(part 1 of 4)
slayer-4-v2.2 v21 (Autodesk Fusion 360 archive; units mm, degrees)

design "slayer-4-v2.2" references "EACHINE CCW TYRO79-1607-2800KV", "M2 x 0.4mm Thread 5mm LONG SOCKET HEAD CAP SCREW", "20x20 Flight Controller", "M3 x 0.5mm Thread 6mm LONG SOCKET HEAD CAP SCREW", "runcam_phoenix_2", "CADDXFPV Ratel 2.1mm", "Slayer Hurricane 4040"
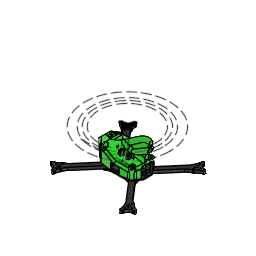
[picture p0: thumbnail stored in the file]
parameter "armstrength" = 5
parameter "d11" = 33
parameter "d12" = 48
parameter "d547" = 2
sketch "center-upper" plane through (0, 0, 0) normal (0, 0, 1) x axis (1, 0, 0)
  line L1 (-93, 0) -> (0, 0)
  line L2 (0, 100) -> (0, 0)
  line L3 (-24, 16.5) -> (-18.1019, 0)
  line L4 (0, 18.1019) -> (-24, 16.5)
  line L5 (0, 18.1019) -> (-10, 10)
  line L6 (-10, 10) -> (-18.1019, 0)
  line L7 (-25.4125, 15.9951) -> (-19.6949, 0)
  line L8 (-22.5875, 17.0049) -> (-16.509, 0)
  line L9 (-11.1655, 10.9443) -> (-20.0325, 0)
  line L10 (-8.8345, 9.0557) -> (-16.1714, 0)
  line L11 (-10.9443, 11.1655) -> (-0.9443, 19.2674)
  line L12 (-9.0557, 8.8345) -> (0.9443, 16.9364)
  line L13 (-35, 0) -> (0, 0)
  line L14 (-22.5875, 17.0049) -> (-24, 16.5)
  line L15 (-25.4125, 15.9951) -> (-24, 16.5)
  line L16 (-11.1655, 10.9443) -> (-10, 10)
  line L17 (-8.8345, 9.0557) -> (-10, 10)
  line L18 (-10.9443, 11.1655) -> (-10, 10)
  line L19 (-9.0557, 8.8345) -> (-10, 10)
  line L20 (-0.9443, 19.2674) -> (0, 18.1019)
  line L21 (0.9443, 16.9364) -> (0, 18.1019)
  line L22 (0.0999, 16.6053) -> (-23.9001, 15.0033)
  line L23 (-0.0999, 19.5986) -> (-24.0999, 17.9967)
  line L24 (-24.0999, 17.9967) -> (-24, 16.5)
  line L25 (-23.9001, 15.0033) -> (-24, 16.5)
  line L26 (-0.0999, 19.5986) -> (0, 18.1019)
  line L27 (0.0999, 16.6053) -> (0, 18.1019)
  line L28 (0, 30) -> (0, 0)
  line L29 (0, 1.5) -> (-18.1019, 1.5)
  line L30 (-18.1019, 1.5) -> (-18.1019, 0)
  line L31 (0, 0) -> (-10, 10)
  line L32 (-14.1459, 2.5) -> (0, 2.5)
  line L33 (-7.5042, 2.5) -> (-10, 10)
  curve K1
  circle C1 centre (-24, 16.5) radius 1.55
  circle C2 centre (0, 18.1019) radius 1.05
  circle C3 centre (-18.1019, 0) radius 1.05
  circle C4 centre (-10, 10) radius 1.05
  circle C5 centre (-24, 16.5) radius 4
  circle C6 centre (0, 18.1019) radius 3
  circle C7 centre (-10, 10) radius 3
  circle C8 centre (-18.1019, 0) radius 3
  point P3 (-24, 16.5)
  point P5 (-24, 16.5)
  point P1 (0, 0)
  point P6 (0, 0)
  point P4 (-18.1019, 0)
  point P8 (0, 0)
  point P2 (0, 18.1019)
  point P11 (-18.1019, 0)
  point P12 (-24, 16.5)
  point P13 (0, 18.1019)
  point P10 (-10, 10)
  point P14 (-10, 10)
  point P20 (-20.0325, 0)
  point P22 (-16.1714, 0)
  point P31 (0, 0)
  point P32 (-35, 0)
  point P33 (-24, 16.5)
  point P34 (-22.5875, 17.0049)
  point P19 (-24, 16.5)
  point P35 (-24, 16.5)
  point P36 (-25.4125, 15.9951)
  point P18 (-22.5875, 17.0049)
  point P16 (-25.4125, 15.9951)
  point P17 (-16.509, 0)
  point P15 (-19.6949, 0)
  point P29 (-10, 10)
  point P37 (-10, 10)
  point P38 (-11.1655, 10.9443)
  point P39 (-10, 10)
  point P40 (-8.8345, 9.0557)
  point P41 (-10, 10)
  point P42 (-10.9443, 11.1655)
  point P43 (-9.0557, 8.8345)
  point P25 (-10.9443, 11.1655)
  point P21 (-11.1655, 10.9443)
  point P23 (-8.8345, 9.0557)
  point P27 (-9.0557, 8.8345)
  point P44 (0, 18.1019)
  point P45 (-0.9443, 19.2674)
  point P46 (0.9443, 16.9364)
  point P24 (-0.9443, 19.2674)
  point P26 (0.9443, 16.9364)
  point P51 (-24.0999, 17.9967)
  point P52 (-24, 16.5)
  point P53 (-23.9001, 15.0033)
  point P49 (-24.0999, 17.9967)
  point P47 (-23.9001, 15.0033)
  point P28 (0, 18.1019)
  point P54 (0, 18.1019)
  point P55 (-0.0999, 19.5986)
  point P56 (0.0999, 16.6053)
  point P50 (-0.0999, 19.5986)
  point P48 (0.0999, 16.6053)
  point P57 (0, 30)
  point P60 (-18.1019, 0)
  point P61 (0, 2.5)
  point P62 (-14.1459, 2.5)
  point P63 (-7.5042, 2.5)
  coincident P3 P5
  coincident P1 P6
  coincident P4 L1
  coincident P1 P8
  coincident P2 L2
  coincident P4 P11
  coincident P3 P12
  coincident P2 P13
  coincident P10 P14
  parallel L3 L7
  parallel L3 L8
  concentric C1 C5
  coincident L1 P20
  parallel L6 L9
  coincident L1 P22
  parallel L6 L10
  parallel L5 L11
  parallel L5 L12
  concentric C2 C6
  concentric C4 C7
  concentric C3 C8
  coincident P1 P31
  coincident L1 P32
  perpendicular L2 L13
  coincident P3 P33
  coincident L8 P34
  perpendicular L8 L14
  coincident P19 P35
  coincident L7 P36
  perpendicular L7 L15
  coincident P18 P34
  coincident P16 P36
  coincident L1 P17
  coincident P15 L13
  coincident P29 P37
  coincident L9 P38
  perpendicular L9 L16
  coincident P10 P39
  coincident L10 P40
  perpendicular L10 L17
  coincident P29 P41
  coincident L11 P42
  perpendicular L11 L18
  coincident L12 P43
  perpendicular L12 L19
  coincident P25 L19
  coincident P21 P38
  coincident P23 P40
  coincident P27 P43
  coincident P2 P44
  coincident L11 P45
  perpendicular L11 L20
  coincident L12 P46
  perpendicular L12 L21
  coincident P24 P45
  coincident P26 P46
  parallel L4 L22
  parallel L4 L23
  coincident L23 P51
  perpendicular L23 L24
  coincident P3 P52
  coincident L22 P53
  perpendicular L22 L25
  coincident P49 P51
  coincident P47 P53
  coincident P28 P54
  coincident L23 P55
  perpendicular L23 L26
  coincident L22 P56
  perpendicular L22 L27
  coincident P50 P55
  coincident P48 P56
  coincident L2 P57
  horizontal L29
  coincident P4 P60
  perpendicular L29 L30
  coincident L28 P61
  coincident L10 P62
  perpendicular L28 L32
  coincident L32 P63
  dimension "d15" distance P2 P4 = 25.6
  dimension "d17" diameter C1 = 3.1
  dimension "d21" diameter C2 = 2.1
  dimension "d24" diameter C3 = 2.1 (= "d21")
  dimension "d27" distance P3 L1 = 16.5 (= "d11 / 2")
  dimension "d28" distance P3 L2 = 24 (= "d12 / 2")
  dimension "d34" diameter C4 = 2.1 (= "d21")
  dimension "d38" distance L2 P10 = 10
  dimension "d39" distance L1 P10 = 10
  dimension "d44" distance L3 L7 = 1.5
  dimension "d45" distance L3 L8 = 1.5 (= "d44")
  dimension "d47" distance L6 L9 = 1.5 (= "d44")
  dimension "d48" distance L6 L10 = 1.5 (= "d44")
  dimension "d49" distance L5 L11 = 1.5 (= "d44")
  dimension "d50" distance L5 L12 = 1.5 (= "d44")
  dimension "d51" diameter C5 = 8
  dimension "d52" diameter C8 = 6
  dimension "d53" diameter C7 = 6
  dimension "d54" diameter C6 = 6
  dimension "d55" distance L4 L23 = 1.5 (= "d44")
  dimension "d56" distance L4 L22 = 1.5 (= "d44")
  dimension "d93" distance L1 L29 = 1.5
  dimension "d118" distance L13 L32 = 2.5
extrude "Extrude2" new body sketch "center-upper" profile of C1 C2 C3 C4 L7 L8 C5 L9 L10 L11 L12 C6 C7 C8 L13 L22 L23 L28 along normal blind 2
fillet "Fillet6" radius 2
fillet "Fillet9" radius 5
fillet "Fillet7" radius 18
fillet "Fillet10" radius 20
mirror "Mirror1" mirrorStitchTolerance 0.1
mirror "Mirror2" mirrorStitchTolerance 0.1
fillet "Fillet8" radius 9
sketch "center-upper-rear-cage" plane through (0, 0, 0) normal (0, 0, -1) x axis (1, 0, 0)
  line L1 (-13.4582, 18.707) -> (-7.8768, 19.0795)
  line L2 (-7.8768, -19.0795) -> (-13.4582, -18.707)
  line L3 (13.4582, -18.707) -> (7.8768, -19.0795)
  line L4 (7.8768, 19.0795) -> (13.4582, 18.707)
  line L5 (19.6919, -8.9044) -> (18.7852, -6.3678)
  line L6 (13.4936, -15.6979) -> (15.3167, -15.5763)
  line L7 (15.3479, -5.782) -> (13.4133, -8.1699)
  line L8 (18.7852, 6.3678) -> (19.6919, 8.9044)
  line L9 (13.4133, 8.1699) -> (15.3479, 5.782)
  line L10 (15.3167, 15.5763) -> (13.4936, 15.6979)
  line L11 (-19.6919, 8.9044) -> (-18.7852, 6.3678)
  line L12 (-13.4936, 15.6979) -> (-15.3167, 15.5763)
  line L13 (-15.3479, 5.782) -> (-13.4133, 8.1699)
  line L14 (-18.7852, -6.3678) -> (-19.6919, -8.9044)
  line L15 (-13.4133, -8.1699) -> (-15.3479, -5.782)
  line L16 (-15.3167, -15.5763) -> (-13.4936, -15.6979)
  line L17 (19, 3) -> (31.9985, 3)
  line L18 (32.2887, 6) -> (20, 6)
  line L19 (34.9985, 7.3474) -> (27.3161, 18.7368)
  line L20 (34.9985, 0) -> (34.9985, 7.3474)
  line L21 (26.9948, 13.8484) -> (32.2887, 6)
  line L22 (31.9985, 0) -> (31.9985, 3)
  line L23 (34.9985, 0) -> (31.9985, 0)
  line L24 (20, 6) -> (19, 3)
  line L25 (27.3161, 18.7368) -> (26.9948, 13.8484)
  circle C1 centre (0, 18.1019) radius 1.05
  arc A1 centre (0, 18.1019) radius 3 clockwise from (-1.2965, 20.8073) to (1.2965, 20.8073)
  arc A2 centre (-9.0756, 37.0396) radius 18 clockwise from (-1.2965, 20.8073) to (-7.8768, 19.0795)
  arc A3 centre (-14.7902, 38.6626) radius 20 clockwise from (-13.4582, 18.707) to (-22.465, 20.1938)
  arc A4 centre (-24, 16.5) radius 4 clockwise from (-26.8498, 13.6931) to (-22.465, 20.1938)
  arc A5 centre (-41.099, -0.3411) radius 20 clockwise from (-26.8498, 13.6931) to (-21.1019, 0)
  arc A6 centre (-41.099, 0.3411) radius 20 clockwise from (-21.1019, 0) to (-26.8498, -13.6931)
  arc A7 centre (-24, -16.5) radius 4 clockwise from (-22.465, -20.1938) to (-26.8498, -13.6931)
  arc A8 centre (-14.7902, -38.6626) radius 20 clockwise from (-22.465, -20.1938) to (-13.4582, -18.707)
  arc A9 centre (-9.0756, -37.0396) radius 18 clockwise from (-7.8768, -19.0795) to (-1.2965, -20.8073)
  arc A10 centre (0, -18.1019) radius 3 clockwise from (1.2965, -20.8073) to (-1.2965, -20.8073)
  arc A11 centre (9.0756, -37.0396) radius 18 clockwise from (1.2965, -20.8073) to (7.8768, -19.0795)
  arc A12 centre (14.7902, -38.6626) radius 20 clockwise from (13.4582, -18.707) to (22.465, -20.1938)
  arc A13 centre (24, -16.5) radius 4 clockwise from (26.8498, -13.6931) to (22.465, -20.1938)
  arc A14 centre (41.099, 0.3411) radius 20 clockwise from (26.8498, -13.6931) to (21.1019, 0)
  arc A15 centre (41.099, -0.3411) radius 20 clockwise from (21.1019, 0) to (26.8498, 13.6931)
  arc A16 centre (24, 16.5) radius 4 clockwise from (22.465, 20.1938) to (26.8498, 13.6931)
  arc A17 centre (14.7902, 38.6626) radius 20 clockwise from (22.465, 20.1938) to (13.4582, 18.707)
  arc A18 centre (9.0756, 37.0396) radius 18 clockwise from (7.8768, 19.0795) to (1.2965, 20.8073)
  arc A19 centre (10, 10) radius 3 clockwise from (8.3417, 7.5) to (7.5, 8.3417)
  arc A20 centre (3.3668, 0) radius 9 clockwise from (8.3417, 7.5) to (8.3417, -7.5)
  arc A21 centre (10, -10) radius 3 clockwise from (7.5, -8.3417) to (8.3417, -7.5)
  arc A22 centre (0, -3.3668) radius 9 clockwise from (7.5, -8.3417) to (-7.5, -8.3417)
  arc A23 centre (-10, -10) radius 3 clockwise from (-8.3417, -7.5) to (-7.5, -8.3417)
  arc A24 centre (-3.3668, 0) radius 9 clockwise from (-8.3417, -7.5) to (-8.3417, 7.5)
  arc A25 centre (-10, 10) radius 3 clockwise from (-7.5, 8.3417) to (-8.3417, 7.5)
  arc A26 centre (0, 3.3668) radius 9 clockwise from (-7.5, 8.3417) to (7.5, 8.3417)
  circle C2 centre (24, -16.5) radius 1.55
  circle C3 centre (10, -10) radius 1.05
  arc A27 centre (14.9837, -10.5874) radius 5 clockwise from (19.6919, -8.9044) to (15.3167, -15.5763)
  arc A28 centre (13.3604, -13.7024) radius 2 clockwise from (13.4936, -15.6979) to (12.0163, -12.2214)
  arc A29 centre (10, -10) radius 3 clockwise from (12.9804, -9.6573) to (12.0163, -12.2214)
  arc A30 centre (14.9673, -9.4289) radius 2 clockwise from (12.9804, -9.6573) to (13.4133, -8.1699)
  arc A31 centre (16.9019, -7.041) radius 2 clockwise from (15.3479, -5.782) to (18.7852, -6.3678)
  arc A32 centre (16.9019, 7.041) radius 2 clockwise from (18.7852, 6.3678) to (15.3479, 5.782)
  arc A33 centre (14.9673, 9.4289) radius 2 clockwise from (13.4133, 8.1699) to (12.9804, 9.6573)
  arc A34 centre (10, 10) radius 3 clockwise from (12.0163, 12.2214) to (12.9804, 9.6573)
  arc A35 centre (13.3604, 13.7024) radius 2 clockwise from (12.0163, 12.2214) to (13.4936, 15.6979)
  arc A36 centre (14.9837, 10.5874) radius 5 clockwise from (15.3167, 15.5763) to (19.6919, 8.9044)
  circle C4 centre (10, 10) radius 1.05
  circle C5 centre (24, 16.5) radius 1.55
  circle C6 centre (18.1019, 0) radius 1.05
  circle C7 centre (-18.1019, 0) radius 1.05
  circle C8 centre (-24, 16.5) radius 1.55
  circle C9 centre (-10, 10) radius 1.05
  arc A37 centre (-14.9837, 10.5874) radius 5 clockwise from (-19.6919, 8.9044) to (-15.3167, 15.5763)
  arc A38 centre (-13.3604, 13.7024) radius 2 clockwise from (-13.4936, 15.6979) to (-12.0163, 12.2214)
  arc A39 centre (-10, 10) radius 3 clockwise from (-12.9804, 9.6573) to (-12.0163, 12.2214)
  arc A40 centre (-14.9673, 9.4289) radius 2 clockwise from (-12.9804, 9.6573) to (-13.4133, 8.1699)
  arc A41 centre (-16.9019, 7.041) radius 2 clockwise from (-15.3479, 5.782) to (-18.7852, 6.3678)
  arc A42 centre (-16.9019, -7.041) radius 2 clockwise from (-18.7852, -6.3678) to (-15.3479, -5.782)
  arc A43 centre (-14.9673, -9.4289) radius 2 clockwise from (-13.4133, -8.1699) to (-12.9804, -9.6573)
  arc A44 centre (-10, -10) radius 3 clockwise from (-12.0163, -12.2214) to (-12.9804, -9.6573)
  arc A45 centre (-13.3604, -13.7024) radius 2 clockwise from (-12.0163, -12.2214) to (-13.4936, -15.6979)
  arc A46 centre (-14.9837, -10.5874) radius 5 clockwise from (-15.3167, -15.5763) to (-19.6919, -8.9044)
  circle C10 centre (-10, -10) radius 1.05
  circle C11 centre (-24, -16.5) radius 1.55
  circle C12 centre (0, -18.1019) radius 1.05
  point P122 (27.3161, 18.7368)
  point P125 (26.9948, 13.8484)
  horizontal L17
  horizontal L18
  midpoint A16 P122
  tangent A16 L19
  vertical L20
  coincident A16 P125
  parallel L19 L21
  perpendicular L17 L22
  perpendicular L20 L23
  dimension "d83" distance L17 L18 = 3
  dimension "d84" distance L19 L21 = 3
  dimension "d85" distance L20 L22 = 3
  dimension "d88" distance L17 L23 = 3
extrude "Extrude3" new body sketch "center-upper-rear-cage" profile of A16 L17 L18 L19 L20 L21 L22 L23 against normal blind 2 bodies "center-upper"
mirror "Mirror3" mirrorStitchTolerance 0.1
combine "Combine1"
fillet "Fillet11" radius 2
extrude "Extrude4" new body sketch "center-upper" profile of C3 C4 L7 L8 L9 L10 L12 C7 C8 L13 L28 L29 L30 L32 L33 no distance stored bodies "puzzle"
sketch "puzzle" plane through (0, 0, -5) normal (0, 0, -1) x axis (1, 0, 0)
  line L1 (0, 0) -> (0, -2.5)
  line L2 (-17.0519, 0) -> (0, 0)
  line L3 (-21.1019, 0) -> (-19.1519, 0)
  line L4 (-12.801, -8.9256) -> (-17.6319, -2.9629)
  line L5 (-7.5042, -2.5) -> (-9.0528, -7.1535)
  line L6 (0, -2.5) -> (-7.5042, -2.5)
  line L7 (-21.1019, -13) -> (-10, -13)
  line L8 (-21.1019, 0) -> (-21.1019, -13)
  line L9 (-15.0963, -6.0926) -> (-24, -16.5)
  line L10 (-5.2336, -20.4063) -> (-29.0797, -0.0054)
  circle C1 centre (-10, -10) radius 1.05
  arc A1 centre (-18.1019, 0) radius 1.05 clockwise from (-17.0519, 0) to (-19.1519, 0)
  arc A2 centre (-18.1019, 0) radius 3 clockwise from (-17.6319, -2.9629) to (-21.1019, 0)
  arc A3 centre (-10, -10) radius 3 clockwise from (-9.0528, -7.1535) to (-12.801, -8.9256)
  arc A4 centre (-7.8796, 0) radius 13.2223 clockwise from (-10.6223, -12.9348) to (-21.1019, 0)
  point P14 (-10.6223, -12.9348)
  point P8 (-21.1019, 0)
  point P13 (-21.1019, 0)
  point P16 (-10, -13)
  tangent A2 A4
  coincident A3 P14
  coincident P8 P13
  tangent A3 A4
  coincident A3 P16
  tangent A3 L7
  parallel L3 L7
  tangent A2 L8
  perpendicular L9 L10
extrude "Extrude6" add sketch "puzzle" profile of A2 L4 A3 A4 L7 L8 L10 no distance stored
fillet "Fillet13" radius 2
sketch "arm" plane through (0, 0, 0) normal (0, 0, -1) x axis (1, 0, 0)
  line L1 (31.9985, -1) -> (31.9985, 1)
  line L2 (23.1491, -3) -> (29.9985, -3)
  line L3 (29.9985, 3) -> (23.1491, 3)
  line L4 (30.1852, 9.1184) -> (28.4467, 11.6958)
  line L5 (25.1483, 6) -> (28.5272, 6)
  line L6 (28.5272, -6) -> (25.1483, -6)
  line L7 (28.4467, -11.6958) -> (30.1852, -9.1184)
  line L8 (-18.7852, -6.3678) -> (-19.6919, -8.9044)
  line L9 (-13.4133, -8.1699) -> (-15.3479, -5.782)
  line L10 (-15.3167, -15.5763) -> (-13.4936, -15.6979)
  line L11 (-19.6919, 8.9044) -> (-18.7852, 6.3678)
  line L12 (-13.4936, 15.6979) -> (-15.3167, 15.5763)
  line L13 (-15.3479, 5.782) -> (-13.4133, 8.1699)
  line L14 (18.7852, 6.3678) -> (19.6919, 8.9044)
  line L15 (13.4133, 8.1699) -> (15.3479, 5.782)
  line L16 (15.3167, 15.5763) -> (13.4936, 15.6979)
  line L17 (19.6919, -8.9044) -> (18.7852, -6.3678)
  line L18 (13.4936, -15.6979) -> (15.3167, -15.5763)
  line L19 (15.3479, -5.782) -> (13.4133, -8.1699)
  line L20 (34.9985, 6.7359) -> (34.9985, -6.7359)
  line L21 (27.3161, 18.7368) -> (34.6566, 7.8543)
  line L22 (7.8768, 19.0795) -> (13.4582, 18.707)
  line L23 (-13.4582, 18.707) -> (-7.8768, 19.0795)
  line L24 (-7.8768, -19.0795) -> (-13.4582, -18.707)
  line L25 (13.4582, -18.707) -> (7.8768, -19.0795)
  line L26 (34.6566, -7.8543) -> (27.3161, -18.7368)
  line L27 (-84.0942, 0) -> (0, 0)
  line L28 (-24, -16.5) -> (-62.0622, -60.9901)
  line L29 (-15.0963, -6.0926) -> (-24, -16.5)
  line L30 (-27.0395, -13.8997) -> (-69.0022, -62.949)
  line L31 (-20.9605, -19.1003) -> (-62.9232, -68.1496)
  line L32 (14.551, -2.5) -> (-14.551, -2.5)
  line L33 (14.551, -2.5) -> (-24.0545, -2.5)
  line L34 (-35, 0) -> (0, 0)
  line L35 (-12.0227, -2.5) -> (-15.0963, -6.0926)
  line L36 (-15.3457, -3) -> (-27.8434, -17.6083)
  line L37 (-9.1275, -2.5) -> (-24.5, -20.4686)
  line L38 (-12.0023, -5.8604) -> (-15.3457, -3)
  line L39 (-62.9232, -68.1496) -> (-69.0022, -62.949)
  line L40 (-62.8385, -51.0203) -> (-62.0622, -60.9901)
  line L41 (-60.5096, -80.9298) -> (-62.0622, -60.9901)
  line L42 (-82.0019, -62.5427) -> (-62.0622, -60.9901)
  line L43 (-52.0924, -60.2138) -> (-62.0622, -60.9901)
  line L44 (-65.4439, -55.7133) -> (-67.7989, -58.4659)
  line L45 (-68.7344, -58.5364) -> (-74.9847, -60.0141)
  line L46 (-68.2741, -64.4471) -> (-74.6778, -63.9546)
  line L47 (-63.0382, -73.9126) -> (-64.5159, -67.6623)
  line L48 (-59.0977, -73.6057) -> (-58.6053, -67.202)
  line L49 (-35.7249, -16.6683) -> (-20.8845, -29.3646)
  arc A1 centre (29.9985, -1) radius 2 clockwise from (31.9985, -1) to (29.9985, -3)
  arc A2 centre (29.9985, 1) radius 2 clockwise from (29.9985, 3) to (31.9985, 1)
  arc A3 centre (26.7887, 10.5774) radius 2 clockwise from (25.1986, 11.7906) to (28.4467, 11.6958)
  arc A4 centre (28.5272, 8) radius 2 clockwise from (30.1852, 9.1184) to (28.5272, 6)
  arc A5 centre (41.099, -0.3411) radius 20 clockwise from (21.1019, 0) to (21.1546, 1.149)
  arc A6 centre (28.5272, -8) radius 2 clockwise from (28.5272, -6) to (30.1852, -9.1184)
  arc A7 centre (26.7887, -10.5774) radius 2 clockwise from (28.4467, -11.6958) to (25.1986, -11.7906)
  arc A8 centre (41.099, 0.3411) radius 20 clockwise from (21.1546, -1.149) to (21.1019, 0)
  circle C1 centre (0, -18.1019) radius 1.05
  circle C2 centre (-24, -16.5) radius 1.55
  circle C3 centre (-10, -10) radius 1.05
  arc A9 centre (-16.9019, -7.041) radius 2 clockwise from (-18.7852, -6.3678) to (-15.3479, -5.782)
  arc A10 centre (-14.9673, -9.4289) radius 2 clockwise from (-13.4133, -8.1699) to (-12.9804, -9.6573)
  arc A11 centre (-10, -10) radius 3 clockwise from (-12.0163, -12.2214) to (-12.9804, -9.6573)
  arc A12 centre (-13.3604, -13.7024) radius 2 clockwise from (-12.0163, -12.2214) to (-13.4936, -15.6979)
  arc A13 centre (-14.9837, -10.5874) radius 5 clockwise from (-15.3167, -15.5763) to (-19.6919, -8.9044)
  arc A14 centre (-14.9837, 10.5874) radius 5 clockwise from (-19.6919, 8.9044) to (-15.3167, 15.5763)
  arc A15 centre (-13.3604, 13.7024) radius 2 clockwise from (-13.4936, 15.6979) to (-12.0163, 12.2214)
  arc A16 centre (-10, 10) radius 3 clockwise from (-12.9804, 9.6573) to (-12.0163, 12.2214)
  arc A17 centre (-14.9673, 9.4289) radius 2 clockwise from (-12.9804, 9.6573) to (-13.4133, 8.1699)
  arc A18 centre (-16.9019, 7.041) radius 2 clockwise from (-15.3479, 5.782) to (-18.7852, 6.3678)
  circle C4 centre (-10, 10) radius 1.05
  circle C5 centre (-24, 16.5) radius 1.55
  circle C6 centre (-18.1019, 0) radius 1.05
  circle C7 centre (18.1019, 0) radius 1.05
  circle C8 centre (24, 16.5) radius 1.55
  circle C9 centre (10, 10) radius 1.05
  arc A19 centre (16.9019, 7.041) radius 2 clockwise from (18.7852, 6.3678) to (15.3479, 5.782)
  arc A20 centre (14.9673, 9.4289) radius 2 clockwise from (13.4133, 8.1699) to (12.9804, 9.6573)
  arc A21 centre (10, 10) radius 3 clockwise from (12.0163, 12.2214) to (12.9804, 9.6573)
  arc A22 centre (13.3604, 13.7024) radius 2 clockwise from (12.0163, 12.2214) to (13.4936, 15.6979)
  arc A23 centre (14.9837, 10.5874) radius 5 clockwise from (15.3167, 15.5763) to (19.6919, 8.9044)
  arc A24 centre (14.9837, -10.5874) radius 5 clockwise from (19.6919, -8.9044) to (15.3167, -15.5763)
  arc A25 centre (13.3604, -13.7024) radius 2 clockwise from (13.4936, -15.6979) to (12.0163, -12.2214)
  arc A26 centre (10, -10) radius 3 clockwise from (12.9804, -9.6573) to (12.0163, -12.2214)
  arc A27 centre (14.9673, -9.4289) radius 2 clockwise from (12.9804, -9.6573) to (13.4133, -8.1699)
  arc A28 centre (16.9019, -7.041) radius 2 clockwise from (15.3479, -5.782) to (18.7852, -6.3678)
  circle C10 centre (10, -10) radius 1.05
  circle C11 centre (24, -16.5) radius 1.55
  arc A29 centre (10, 10) radius 3 clockwise from (8.3417, 7.5) to (7.5, 8.3417)
  arc A30 centre (3.3668, 0) radius 9 clockwise from (8.3417, 7.5) to (8.3417, -7.5)
  arc A31 centre (10, -10) radius 3 clockwise from (7.5, -8.3417) to (8.3417, -7.5)
  arc A32 centre (0, -3.3668) radius 9 clockwise from (7.5, -8.3417) to (-7.5, -8.3417)
  arc A33 centre (-10, -10) radius 3 clockwise from (-8.3417, -7.5) to (-7.5, -8.3417)
  arc A34 centre (-3.3668, 0) radius 9 clockwise from (-8.3417, -7.5) to (-8.3417, 7.5)
  arc A35 centre (-10, 10) radius 3 clockwise from (-7.5, 8.3417) to (-8.3417, 7.5)
  arc A36 centre (0, 3.3668) radius 9 clockwise from (-7.5, 8.3417) to (7.5, 8.3417)
  circle C12 centre (0, 18.1019) radius 1.05
  arc A37 centre (32.9985, -6.7359) radius 2 clockwise from (34.9985, -6.7359) to (34.6566, -7.8543)
  arc A38 centre (32.9985, 6.7359) radius 2 clockwise from (34.6566, 7.8543) to (34.9985, 6.7359)
  arc A39 centre (24, 16.5) radius 4 clockwise from (22.465, 20.1938) to (27.3161, 18.7368)
  arc A40 centre (14.7902, 38.6626) radius 20 clockwise from (22.465, 20.1938) to (13.4582, 18.707)
  arc A41 centre (9.0756, 37.0396) radius 18 clockwise from (7.8768, 19.0795) to (1.2965, 20.8073)
  arc A42 centre (0, 18.1019) radius 3 clockwise from (-1.2965, 20.8073) to (1.2965, 20.8073)
  arc A43 centre (-9.0756, 37.0396) radius 18 clockwise from (-1.2965, 20.8073) to (-7.8768, 19.0795)
  arc A44 centre (-14.7902, 38.6626) radius 20 clockwise from (-13.4582, 18.707) to (-22.465, 20.1938)
  arc A45 centre (-24, 16.5) radius 4 clockwise from (-26.8498, 13.6931) to (-22.465, 20.1938)
  arc A46 centre (-41.099, -0.3411) radius 20 clockwise from (-26.8498, 13.6931) to (-21.1019, 0)
  arc A47 centre (-41.099, 0.3411) radius 20 clockwise from (-21.1019, 0) to (-26.8498, -13.6931)
  arc A48 centre (-24, -16.5) radius 4 clockwise from (-22.465, -20.1938) to (-26.8498, -13.6931)
  arc A49 centre (-14.7902, -38.6626) radius 20 clockwise from (-22.465, -20.1938) to (-13.4582, -18.707)
  arc A50 centre (-9.0756, -37.0396) radius 18 clockwise from (-7.8768, -19.0795) to (-1.2965, -20.8073)
  arc A51 centre (0, -18.1019) radius 3 clockwise from (1.2965, -20.8073) to (-1.2965, -20.8073)
  arc A52 centre (9.0756, -37.0396) radius 18 clockwise from (1.2965, -20.8073) to (7.8768, -19.0795)
  arc A53 centre (14.7902, -38.6626) radius 20 clockwise from (13.4582, -18.707) to (22.465, -20.1938)
  arc A54 centre (24, -16.5) radius 4 clockwise from (27.3161, -18.7368) to (22.465, -20.1938)
  circle C13 centre (-24, -16.5) radius 1.55
  circle C14 centre (-62.0622, -60.9901) radius 50.8
  circle C15 centre (-24, -16.5) radius 4
  circle C16 centre (-62.0622, -60.9901) radius 2.5
  circle C17 centre (-62.528, -55.0082) radius 1.075
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  point P1 (0, 0)
  point P148 (0, 0)
  point P147 (-62.0622, -60.9901)
  point P149 (-62.0622, -60.9901)
  point P146 (-24, -16.5)
  point P151 (-24, -16.5)
  point P156 (14.551, -2.5)
  point P158 (14.551, -2.5)
  point P164 (-12.0227, -2.5)
  point P166 (-9.1275, -2.5)
  point P167 (-12.0023, -5.8604)
  point P168 (-15.3457, -3)
  point P165 (-15.3457, -3)
  point P169 (-62.0622, -60.9901)
  point P170 (-62.0622, -60.9901)
  point P173 (-62.0622, -60.9901)
  point P176 (-62.528, -55.0082)
  point P177 (-61.5964, -66.972)
  point P178 (-68.0441, -61.4559)
  point P184 (-74.5245, -61.9605)
  point P189 (-61.0918, -73.4524)
  point P162 (-27.8434, -17.6083)
  point P163 (-24.5, -20.4686)
  point P196 (-27.0395, -13.8997)
  point P195 (-20.9605, -19.1003)
  point P171 (-62.8385, -51.0203)
  point P172 (-60.5096, -80.9298)
  point P174 (-82.0019, -62.5427)
  point P175 (-52.0924, -60.2138)
  point P181 (-68.0441, -61.4559)
  point P180 (-61.5964, -66.972)
  point P161 (-24, -16.5)
  horizontal L27
  coincident P1 P148
  coincident P147 P149
  coincident P146 P151
  parallel L28 L29
  parallel L28 L30
  parallel L28 L31
  coincident P156 P158
  parallel L32 L33
  concentric C13 C15
  parallel L29 L35
  coincident L33 P164
  parallel L29 L36
  coincident L33 P166
  parallel L29 L37
  coincident L37 P167
  perpendicular L30 L39
  coincident L38 P168
  perpendicular L36 L38
  coincident P165 L36
  coincident P149 P169
  coincident P169 P170
  coincident P147 P173
  coincident L40 P176
  coincident L41 P177
  coincident L42 P178
  perpendicular L40 L42
  perpendicular L41 L42
  perpendicular L41 L43
  parallel L31 L44
  coincident L42 P184
  coincident L41 P189
  coincident C15 P162
  coincident C15 P163
  coincident C15 P196
  coincident C15 P195
  perpendicular L30 L49
  dimension "d105" diameter C14 = 101.6
  dimension "d114" distance L28 L30 = 4
  dimension "d115" distance L29 L31 = 4 (= "d114")
  dimension "d117" distance L33 L34 = 2.5
  dimension "d121" diameter C15 = 8
  dimension "d133" distance L27 P165 = 3
  dimension "d155" diameter C16 = 5
  dimension "d156" distance P170 P171 = 10
  dimension "d157" distance P170 P172 = 20
  dimension "d158" distance P173 P174 = 20
  dimension "d159" distance P173 P175 = 10
  dimension "d160" diameter C17 = 2.15
  dimension "d162" diameter = 2.15 (= "d160")
  dimension "d163" diameter = 2.15 (= "d160")
  dimension "d164" distance P147 P176 = 6
  dimension "d165" distance P147 P178 = 6 (= "d164")
  dimension "d167" distance P147 P177 = 6 (= "d164")
  dimension "d168" angle L28 L40 = 45
  dimension "d169" diameter = 6
  dimension "d170" diameter = 6 (= "d169")
  dimension "d172" diameter = 6 (= "d169")
  dimension "d173" distance P147 L39 = 6
  dimension "d175" distance P147 L44 = 6 (= "d173")
  dimension "d181" diameter = 4
  dimension "d182" distance P181 P184 = 6.5
  dimension "d183" diameter = 4 (= "d181")
  dimension "d184" distance P180 P189 = 6.5 (= "d182")
  dimension "d711" diameter = 114.3
  dimension "d801" diameter = 152.4 (= "6")
  dimension "d802" diameter = 127 (= "5")
  dimension "d803" distance P161 L49 = 7.75
  dimension "d804" distance P147 L49 = 50.8 (= "d105 / 2")
extrude "Extrude5" new body sketch "arm" along normal blind 5 (= "armstrength") bodies "arm-fr"
fillet "Fillet14" radius 20
fillet "Fillet18" radius 20
fillet "Fillet132" radius 4
fillet "Fillet19" radius 10
combine "Combine2"
sketch "puzzle-reduction" plane through (0, 0, -5) normal (0, 0, -1) x axis (1, 0, 0)
  line L1 (-16.3271, -10.9155) -> (-12.0023, -5.8604)
  line L2 (-7.9596, -3.8685) -> (-8.5531, -5.6519)
  line L3 (0, -2.5) -> (-6.0619, -2.5)
  line L4 (0, 0) -> (0, -2.5)
  line L5 (-17.0519, 0) -> (0, 0)
  line L6 (-21.1019, 0) -> (-19.1519, 0)
  line L7 (-15.3457, -3) -> (-19.6705, -8.0552)
  line L8 (-12.0023, -5.8604) -> (-15.3457, -3)
  line L9 (-13, -2.5) -> (0, -2.5)
  line L10 (-21.1019, -2.15) -> (-18.1019, -2.15)
  line L11 (-12.15, -13) -> (-12.15, -10)
  line L12 (-8.5531, -5.6519) -> (-11.4831, -8.4434)
  line L13 (-15.0133, -12.0395) -> (-16.3271, -10.9155)
  line L14 (-10, -13) -> (-12.413, -13)
  line L15 (-21.1019, -4.9885) -> (-21.1019, 0)
  line L16 (-19.6705, -8.0552) -> (-19.7023, -8.028)
  arc A1 centre (-10, -10) radius 3 clockwise from (-7.9932, -7.77) to (-10, -13)
  arc A2 centre (-6.6554, -6.2834) radius 2 clockwise from (-7.9932, -7.77) to (-8.5531, -5.6519)
  arc A3 centre (-6.0619, -4.5) radius 2 clockwise from (-7.9596, -3.8685) to (-6.0619, -2.5)
  arc A4 centre (-18.1019, 0) radius 1.05 clockwise from (-17.0519, 0) to (-19.1519, 0)
  circle C1 centre (-10, -10) radius 1.05
  circle C2 centre (-10, -10) radius 2.9998
  circle C3 centre (-18.1019, 0) radius 3
  circle C4 centre (-18.1019, 0) radius 2.15
  circle C5 centre (-10, -10) radius 2.15
  arc A5 centre (-12.413, -9) radius 4 clockwise from (-12.413, -13) to (-15.0133, -12.0395)
  arc A6 centre (-17.1019, -4.9885) radius 4 clockwise from (-19.7023, -8.028) to (-21.1019, -4.9885)
  point P12 (0, -2.5)
  point P21 (0, -2.5)
  point P17 (-21.1019, 0)
  point P26 (-18.1019, -2.15)
  point P28 (-12.15, -10)
  point P30 (-11.4831, -8.4434)
  point P29 (-12.15, -13)
  point P7 (-8.5531, -5.6519)
  point P37 (-8.5531, -5.6519)
  point P27 (-21.1019, -2.15)
  concentric A1 C2
  coincident P12 P21
  perpendicular L4 L9
  concentric A4 C3
  coincident P17 C3
  concentric A4 C4
  concentric C2 C5
  coincident C4 P26
  tangent C4 L10
  horizontal L10
  coincident C5 P28
  tangent C5 L11
  vertical L11
  coincident C5 P30
  tangent C5 L12
  coincident P29 L14
  coincident P7 P37
  coincident P27 L15
  dimension "d151" diameter C4 = 4.3
  dimension "d152" diameter C5 = 4.3
extrude "Extrude7" cut sketch "puzzle-reduction" profile of A1 A2 L5 A4 L6 C1 C2 C3 C4 C5 L10 L11 L12 L14 L15 against normal blind 2
fillet "Fillet15" radius 2
fillet "Fillet16" radius 2
mirror "Mirror6" mirrorStitchTolerance 0.1
mirror "Mirror7" mirrorStitchTolerance 0.1
sketch "puzzle reduction-2" plane through (0, 0, 0) normal (0, 0, 1) x axis (-1, 0, 0)
  line L1 (16.6459, 4.5197) -> (19.6705, 8.0552)
  line L2 (13.522, 4.5602) -> (13.826, 4.3002)
  line L3 (16.3271, 10.9155) -> (13.3025, 7.3801)
  line L4 (7.9596, 3.8685) -> (8.5531, 5.6519)
  line L5 (0, 2.5) -> (6.0619, 2.5)
  line L6 (-8.5531, 5.6519) -> (-7.9596, 3.8685)
  line L7 (-13.3025, 7.3801) -> (-16.3271, 10.9155)
  line L8 (-13.826, 4.3002) -> (-13.522, 4.5602)
  line L9 (-19.6705, 8.0552) -> (-16.6459, 4.5197)
  line L10 (-16.6459, -4.5197) -> (-19.6705, -8.0552)
  line L11 (-13.522, -4.5602) -> (-13.826, -4.3002)
  line L12 (-16.3271, -10.9155) -> (-13.3025, -7.3801)
  line L13 (-7.9596, -3.8685) -> (-8.5531, -5.6519)
  line L14 (6.0619, -2.5) -> (0, -2.5)
  line L15 (8.5531, -5.6519) -> (7.9596, -3.8685)
  line L16 (13.3025, -7.3801) -> (16.3271, -10.9155)
  line L17 (13.826, -4.3002) -> (13.522, -4.5602)
  line L18 (19.6705, -8.0552) -> (16.6459, -4.5197)
  line L19 (-11.3, 0) -> (11.3, 0)
  line L20 (8.3152, -4.9371) -> (12.5467, -1.5639)
  line L21 (8.3152, 4.9371) -> (12.5467, 1.5639)
  line L22 (0, -20) -> (0, -2.5)
  line L23 (-8.3152, -4.9371) -> (-12.5467, -1.5639)
  line L24 (-8.3152, 4.9371) -> (-12.5467, 1.5639)
  line L25 (-6.0619, 2.5) -> (0, 2.5)
  line L26 (0, -2.5) -> (-6.0619, -2.5)
  line L27 (21.1019, 4.9885) -> (21.1019, -4.9885)
  line L28 (19.6705, 8.0552) -> (19.7023, 8.028)
  line L29 (15.0133, 12.0395) -> (16.3271, 10.9155)
  line L30 (10, 13) -> (12.413, 13)
  line L31 (-12.413, 13) -> (-10, 13)
  line L32 (-16.3271, 10.9155) -> (-15.0133, 12.0395)
  line L33 (-19.7023, 8.028) -> (-19.6705, 8.0552)
  line L34 (-21.1019, -4.9885) -> (-21.1019, 4.9885)
  line L35 (-19.6705, -8.0552) -> (-19.7023, -8.028)
  line L36 (-15.0133, -12.0395) -> (-16.3271, -10.9155)
  line L37 (-10, -13) -> (-12.413, -13)
  line L38 (12.413, -13) -> (10, -13)
  line L39 (16.3271, -10.9155) -> (15.0133, -12.0395)
  line L40 (19.7023, -8.028) -> (19.6705, -8.0552)
  circle C1 centre (-10, -10) radius 1.05
  circle C2 centre (-10, 10) radius 1.05
  circle C3 centre (-18.1019, 0) radius 1.05
  circle C4 centre (18.1019, 0) radius 1.05
  circle C5 centre (10, 10) radius 1.05
  arc A1 centre (15.1262, 5.8199) radius 2 clockwise from (16.6459, 4.5197) to (13.826, 4.3002)
  arc A2 centre (14.8222, 6.0799) radius 2 clockwise from (13.522, 4.5602) to (13.3025, 7.3801)
  arc A3 centre (10, 10) radius 3 clockwise from (7.9932, 7.77) to (10, 13)
  arc A4 centre (6.6554, 6.2834) radius 2 clockwise from (7.9932, 7.77) to (8.5531, 5.6519)
  arc A5 centre (6.0619, 4.5) radius 2 clockwise from (7.9596, 3.8685) to (6.0619, 2.5)
  arc A6 centre (-6.0619, 4.5) radius 2 clockwise from (-6.0619, 2.5) to (-7.9596, 3.8685)
  arc A7 centre (-6.6554, 6.2834) radius 2 clockwise from (-8.5531, 5.6519) to (-7.9932, 7.77)
  arc A8 centre (-10, 10) radius 3 clockwise from (-10, 13) to (-7.9932, 7.77)
  arc A9 centre (-14.8222, 6.0799) radius 2 clockwise from (-13.3025, 7.3801) to (-13.522, 4.5602)
  arc A10 centre (-15.1262, 5.8199) radius 2 clockwise from (-13.826, 4.3002) to (-16.6459, 4.5197)
  arc A11 centre (-15.1262, -5.8199) radius 2 clockwise from (-16.6459, -4.5197) to (-13.826, -4.3002)
  arc A12 centre (-14.8222, -6.0799) radius 2 clockwise from (-13.522, -4.5602) to (-13.3025, -7.3801)
  arc A13 centre (-10, -10) radius 3 clockwise from (-7.9932, -7.77) to (-10, -13)
  arc A14 centre (-6.6554, -6.2834) radius 2 clockwise from (-7.9932, -7.77) to (-8.5531, -5.6519)
  arc A15 centre (-6.0619, -4.5) radius 2 clockwise from (-7.9596, -3.8685) to (-6.0619, -2.5)
  arc A16 centre (6.0619, -4.5) radius 2 clockwise from (6.0619, -2.5) to (7.9596, -3.8685)
  arc A17 centre (6.6554, -6.2834) radius 2 clockwise from (8.5531, -5.6519) to (7.9932, -7.77)
  arc A18 centre (10, -10) radius 3 clockwise from (10, -13) to (7.9932, -7.77)
  arc A19 centre (14.8222, -6.0799) radius 2 clockwise from (13.3025, -7.3801) to (13.522, -4.5602)
  arc A20 centre (15.1262, -5.8199) radius 2 clockwise from (13.826, -4.3002) to (16.6459, -4.5197)
  circle C6 centre (10, -10) radius 1.05
  circle C7 centre (11.3, 0) radius 2
  circle C8 centre (-11.3, 0) radius 2
  arc A21 centre (17.1019, 4.9885) radius 4 clockwise from (19.7023, 8.028) to (21.1019, 4.9885)
  arc A22 centre (12.413, 9) radius 4 clockwise from (12.413, 13) to (15.0133, 12.0395)
  arc A23 centre (-12.413, 9) radius 4 clockwise from (-15.0133, 12.0395) to (-12.413, 13)
  arc A24 centre (-17.1019, 4.9885) radius 4 clockwise from (-21.1019, 4.9885) to (-19.7023, 8.028)
  arc A25 centre (-17.1019, -4.9885) radius 4 clockwise from (-19.7023, -8.028) to (-21.1019, -4.9885)
  arc A26 centre (-12.413, -9) radius 4 clockwise from (-12.413, -13) to (-15.0133, -12.0395)
  arc A27 centre (12.413, -9) radius 4 clockwise from (15.0133, -12.0395) to (12.413, -13)
  arc A28 centre (17.1019, -4.9885) radius 4 clockwise from (21.1019, -4.9885) to (19.7023, -8.028)
  point P68 (11.3, 0)
  point P70 (11.3, 0)
  point P69 (-11.3, 0)
  point P71 (-11.3, 0)
  point P72 (12.5467, -1.5639)
  point P73 (8.3152, -4.9371)
  point P74 (12.5467, 1.5639)
  point P75 (8.3152, 4.9371)
  point P78 (-12.5467, -1.5639)
  point P79 (-8.3152, -4.9371)
  point P80 (-12.5467, 1.5639)
  point P81 (-8.3152, 4.9371)
  point P1 (0, 0)
  coincident P68 P70
  coincident P69 P71
  horizontal L19
  coincident C7 P72
  coincident L15 P73
  tangent C7 L20
  symmetric L19 P72 P74
  symmetric L19 P73 P75
  symmetric P72 L22 P78
  symmetric P73 L22 P79
  symmetric P74 L22 P80
  symmetric P75 L22 P81
  dimension "d145" diameter C7 = 4
  dimension "d146" distance P1 P68 = 11.3
  dimension "d147" distance P1 P69 = 11.3 (= "d146")
  dimension "d148" diameter C8 = 4 (= "d145")
extrude "Extrude8" cut sketch "puzzle reduction-2" profile of C7 C8 against normal blind 4
fillet "Fillet17" radius 2.1
mirror "Mirror8" mirrorStitchTolerance 0.1 bodies "arm-fl"
mirror "Mirror9" mirrorStitchTolerance 0.1 bodies "arm-rl", "arm-rr"
sketch "center-lower" plane through (0, 0, -5) normal (0, 0, -1) x axis (1, 0, 0)
  line L1 (-16.6459, -4.5197) -> (-19.6705, -8.0552)
  line L2 (-13.522, -4.5602) -> (-13.826, -4.3002)
  line L3 (-16.3271, -10.9155) -> (-13.3025, -7.3801)
  line L4 (-8.9138, -5.9956) -> (-11.4831, -8.4434)
  line L5 (0, -2.5) -> (-6.0619, -2.5)
  line L6 (11.4831, -8.4434) -> (8.9138, -5.9956)
  line L7 (13.3025, -7.3801) -> (16.3271, -10.9155)
  line L8 (13.826, -4.3002) -> (13.522, -4.5602)
  line L9 (19.6705, -8.0552) -> (16.6459, -4.5197)
  line L10 (18.1019, -2.15) -> (19.1019, -2.15)
  line L11 (19.1019, 2.15) -> (18.1019, 2.15)
  line L12 (16.6459, 4.5197) -> (19.6705, 8.0552)
  line L13 (13.522, 4.5602) -> (13.826, 4.3002)
  line L14 (16.3271, 10.9155) -> (13.3025, 7.3801)
  line L15 (8.9138, 5.9956) -> (11.4831, 8.4434)
  line L16 (0, 2.5) -> (6.0619, 2.5)
  line L17 (-11.4831, 8.4434) -> (-8.9138, 5.9956)
  line L18 (-13.3025, 7.3801) -> (-16.3271, 10.9155)
  line L19 (-13.826, 4.3002) -> (-13.522, 4.5602)
  line L20 (-19.6705, 8.0552) -> (-16.6459, 4.5197)
  line L21 (-18.1019, 2.15) -> (-19.1019, 2.15)
  line L22 (-19.1019, -2.15) -> (-18.1019, -2.15)
  line L23 (-40.0019, -6) -> (-40.0019, 6)
  line L24 (-61.9019, 0) -> (-18.1019, 0)
  line L25 (-26.0782, 18.8035) -> (-40.0019, 6)
  line L26 (-58.9176, 6) -> (-40.0019, 6)
  line L27 (-24, 0) -> (-24, 16.5)
  line L28 (-10, 14) -> (-24, 16.5)
  line L29 (-25.5, 16.5) -> (-25.5, 0)
  line L30 (-25.5, 16.5) -> (-24, 16.5)
  line L31 (-22.5, 16.5) -> (-22.5, 0)
  line L32 (-24, 16.5) -> (-22.5, 16.5)
  line L33 (-10, 16.0316) -> (-23.6484, 18.4689)
  line L34 (-20.9414, 13.9222) -> (-24.3516, 14.5311)
  line L35 (-24, 16.5) -> (-23.6484, 18.4689)
  line L36 (-24, 16.5) -> (-24.3516, 14.5311)
  line L37 (0, 21.814) -> (0, 0)
  line L38 (-10, 11.9684) -> (-20.9414, 13.9222)
  line L39 (-22.5, 0) -> (-25.5, 0)
  line L40 (18.1019, 0) -> (-18.1019, 0)
  curve K1 (-15, 0) -> (-26.0663, 13.075)
  curve K2 (-24.9, 12.3) -> (-27.2326, 13.8501)
  curve K3 (-15, -1.2506) -> (-15, 1.2506)
  curve K4 (-9.2694, 0) -> (-21.7934, 19.8363)
  curve K5 (-9.2694, -2) -> (-9.2694, 2)
  line L41 (-9.2694, 0) -> (-15, 0)
  curve K6 (-20.7836, 18.9996) -> (-22.8032, 20.673)
  line L42 (-7.9596, -3.8685) -> (-8.3957, -5.1791)
  line L43 (8.3957, -5.1791) -> (7.9596, -3.8685)
  line L44 (7.9596, 3.8685) -> (8.3957, 5.1791)
  line L45 (-8.3957, 5.1791) -> (-7.9596, 3.8685)
  line L46 (-10.0777, 4) -> (0, 4)
  line L47 (0, 0) -> (0, 4)
  line L48 (0, 0) -> (-9.2694, 0)
  line L49 (-25.5, 3) -> (-37.0019, 3)
  line L50 (-25.5, 6) -> (-35.5698, 6)
  line L51 (-37.0019, 3) -> (-37.0019, 0)
  line L52 (-27.0127, 13.8687) -> (-35.5698, 6)
  line L53 (-37.0019, 0) -> (-40.0019, 0)
  line L54 (0, 16.0316) -> (-10, 16.0316)
  line L55 (0, 11.9684) -> (-10, 11.9684)
  line L56 (0, 11.9684) -> (0, 16.0316)
  line L57 (6.0619, -2.5) -> (0, -2.5)
  line L58 (-6.0619, 2.5) -> (0, 2.5)
  line L59 (-21.1019, -4.9885) -> (-21.1019, -4.15)
  line L60 (-19.6705, -8.0552) -> (-19.7023, -8.028)
  line L61 (-15.4502, -11.6658) -> (-16.3271, -10.9155)
  line L62 (-12.15, -10) -> (-12.15, -10.146)
  line L63 (12.15, -10.146) -> (12.15, -10)
  line L64 (16.3271, -10.9155) -> (15.4502, -11.6658)
  line L65 (19.7023, -8.028) -> (19.6705, -8.0552)
  line L66 (21.1019, -4.15) -> (21.1019, -4.9885)
  line L67 (21.1019, 4.9885) -> (21.1019, 4.15)
  line L68 (19.6705, 8.0552) -> (19.7023, 8.028)
  line L69 (15.4502, 11.6658) -> (16.3271, 10.9155)
  line L70 (12.15, 10) -> (12.15, 10.146)
  line L71 (-12.15, 10.146) -> (-12.15, 10)
  line L72 (-16.3271, 10.9155) -> (-15.4502, 11.6658)
  line L73 (-19.7023, 8.028) -> (-19.6705, 8.0552)
  line L74 (-21.1019, 4.15) -> (-21.1019, 4.9885)
  arc A1 centre (-15.1262, -5.8199) radius 2 clockwise from (-16.6459, -4.5197) to (-13.826, -4.3002)
  arc A2 centre (-14.8222, -6.0799) radius 2 clockwise from (-13.522, -4.5602) to (-13.3025, -7.3801)
  arc A3 centre (-10, -10) radius 2.15 clockwise from (-12.15, -10) to (-11.4831, -8.4434)
  arc A4 centre (10, -10) radius 2.15 clockwise from (11.4831, -8.4434) to (12.15, -10)
  arc A5 centre (14.8222, -6.0799) radius 2 clockwise from (13.3025, -7.3801) to (13.522, -4.5602)
  arc A6 centre (15.1262, -5.8199) radius 2 clockwise from (13.826, -4.3002) to (16.6459, -4.5197)
  arc A7 centre (18.1019, 0) radius 2.15 clockwise from (18.1019, -2.15) to (18.1019, 2.15)
  arc A8 centre (15.1262, 5.8199) radius 2 clockwise from (16.6459, 4.5197) to (13.826, 4.3002)
  arc A9 centre (14.8222, 6.0799) radius 2 clockwise from (13.522, 4.5602) to (13.3025, 7.3801)
  arc A10 centre (10, 10) radius 2.15 clockwise from (12.15, 10) to (11.4831, 8.4434)
  arc A11 centre (-10, 10) radius 2.15 clockwise from (-11.4831, 8.4434) to (-12.15, 10)
  arc A12 centre (-14.8222, 6.0799) radius 2 clockwise from (-13.3025, 7.3801) to (-13.522, 4.5602)
  arc A13 centre (-15.1262, 5.8199) radius 2 clockwise from (-13.826, 4.3002) to (-16.6459, 4.5197)
  arc A14 centre (-18.1019, 0) radius 2.15 clockwise from (-18.1019, 2.15) to (-18.1019, -2.15)
  circle C1 centre (-24, 16.5) radius 1.55
  circle C2 centre (-18.1019, 0) radius 1.05
  circle C3 centre (-10, 10) radius 1.05
  circle C4 centre (0, 18.1019) radius 1.05
  circle C5 centre (10, 10) radius 1.05
  circle C6 centre (18.1019, 0) radius 1.05
  circle C7 centre (-24, 16.5) radius 4
  arc A15 centre (-10.2934, -4.5476) radius 2 clockwise from (-8.3957, -5.1791) to (-8.9138, -5.9956)
  arc A16 centre (-6.0619, -4.5) radius 2 clockwise from (-7.9596, -3.8685) to (-6.0619, -2.5)
  arc A17 centre (6.0619, -4.5) radius 2 clockwise from (6.0619, -2.5) to (7.9596, -3.8685)
  arc A18 centre (10.2934, -4.5476) radius 2 clockwise from (8.9138, -5.9956) to (8.3957, -5.1791)
  arc A19 centre (10.2934, 4.5476) radius 2 clockwise from (8.3957, 5.1791) to (8.9138, 5.9956)
  arc A20 centre (6.0619, 4.5) radius 2 clockwise from (7.9596, 3.8685) to (6.0619, 2.5)
  arc A21 centre (-6.0619, 4.5) radius 2 clockwise from (-6.0619, 2.5) to (-7.9596, 3.8685)
  arc A22 centre (-10.2934, 4.5476) radius 2 clockwise from (-8.9138, 5.9956) to (-8.3957, 5.1791)
  arc A23 centre (-19.1019, -4.15) radius 2 clockwise from (-21.1019, -4.15) to (-19.1019, -2.15)
  arc A24 centre (-17.1019, -4.9885) radius 4 clockwise from (-19.7023, -8.028) to (-21.1019, -4.9885)
  arc A25 centre (-14.15, -10.146) radius 2 clockwise from (-12.15, -10.146) to (-15.4502, -11.6658)
  arc A26 centre (14.15, -10.146) radius 2 clockwise from (15.4502, -11.6658) to (12.15, -10.146)
  arc A27 centre (17.1019, -4.9885) radius 4 clockwise from (21.1019, -4.9885) to (19.7023, -8.028)
  arc A28 centre (19.1019, -4.15) radius 2 clockwise from (19.1019, -2.15) to (21.1019, -4.15)
  arc A29 centre (19.1019, 4.15) radius 2 clockwise from (21.1019, 4.15) to (19.1019, 2.15)
  arc A30 centre (17.1019, 4.9885) radius 4 clockwise from (19.7023, 8.028) to (21.1019, 4.9885)
  arc A31 centre (14.15, 10.146) radius 2 clockwise from (12.15, 10.146) to (15.4502, 11.6658)
  arc A32 centre (-14.15, 10.146) radius 2 clockwise from (-15.4502, 11.6658) to (-12.15, 10.146)
  arc A33 centre (-17.1019, 4.9885) radius 4 clockwise from (-21.1019, 4.9885) to (-19.7023, 8.028)
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  point P65 (-18.1019, 0)
  point P72 (-18.1019, 0)
  point P64 (-24, 16.5)
  point P77 (-24, 16.5)
  point P78 (-24, 0)
  point P76 (-24, 16.5)
  point P79 (-24, 16.5)
  point P81 (-25.5, 0)
  point P83 (-24, 16.5)
  point P84 (-22.5, 0)
  point P1 (0, 0)
  point P88 (0, 0)
  point P90 (-20.9414, 13.9222)
  point P32 (18.1019, 0)
  point P91 (18.1019, 0)
  point P92 (-26.0663, 13.075)
  point P93 (-15, 0)
  point P98 (-21.7934, 19.8363)
  point P99 (-9.2694, 0)
  point P120 (0, 4)
  point P121 (-10.0777, 4)
  point P122 (0, 0)
  point P123 (0, 0)
  point P125 (-25.5, 3)
  point P127 (-25.5, 6)
  point P128 (-37.0019, 0)
  point P129 (-27.0127, 13.8687)
  point P130 (-40.0019, 0)
  point P131 (-10, 16.0316)
  point P132 (-10, 11.9684)
  point P80 (-10, 14)
  point P70 (-40.0019, 6)
  point P71 (-40.0019, -6)
  vertical L23
  coincident P65 P72
  horizontal L24
  midpoint L23 L24
  horizontal L26
  concentric C1 C7
  coincident P64 P77
  coincident L24 P78
  perpendicular L24 L27
  coincident P76 P79
  coincident L24 P81
  perpendicular L24 L29
  coincident P76 P83
  perpendicular L27 L30
  coincident L24 P84
  perpendicular L27 L32
  parallel L27 L31
  perpendicular L28 L35
  perpendicular L28 L36
  parallel L28 L34
  parallel L28 L33
  coincident P1 P88
  vertical L37
  coincident C7 P90
  parallel L28 L38
  coincident P32 P91
  coincident C7 P92
  coincident L40 P93
  midpoint P92 K2
  midpoint P93 K3
  parallel L37 K3
  coincident C7 P98
  coincident L40 P99
  midpoint P99 K5
  parallel L37 K5
  midpoint P98 K6
  coincident L37 P120
  coincident K4 P121
  perpendicular L37 L46
  coincident P1 P122
  coincident P1 P123
  coincident L29 P125
  perpendicular L29 L49
  coincident L29 P127
  perpendicular L29 L50
  coincident L24 P128
  perpendicular L24 L51
  coincident C7 P129
  parallel L25 L52
  midpoint L23 P130
  vertical P131 P132
  vertical P80 P131
  parallel L37 L56
  parallel L40 L55
  parallel L54 L55
  dimension "d189" distance P65 L23 = 21.9
  dimension "d190" distance P70 P71 = 12
  dimension "d191" angle L25 L26 = 137.4
  dimension "d192" distance L27 L29 = 1.5
  dimension "d193" diameter C7 = 8
  dimension "d194" distance L27 L31 = 1.5 (= "d192")
  dimension "d195" distance L28 L33 = 2
  dimension "d196" distance L28 L34 = 2
  dimension "d224" distance L40 L46 = 4
  dimension "d228" distance L24 L49 = 3
  dimension "d229" distance L49 L50 = 3
  dimension "d230" distance L23 L51 = 3
  dimension "d231" distance L25 L52 = 3
extrude "Extrude9" new body sketch "center-lower" profile of L18 A12 L19 A13 L20 C1 C7 L29 L31 L33 L34 L38 L39 K1 K4 L41 A21 L45 L46 L47 L48 L54 L55 L56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 along normal blind 2
fillet "Fillet20" radius 24
fillet "Fillet21" radius 2.5
mirror "Mirror11" mirrorStitchTolerance 0.1
sketch "center-lower-holes" plane through (0, 0, -7) normal (0, 0, -1) x axis (1, 0, 0)
  line L1 (-10, 16.0316) -> (10, 16.0316)
  line L2 (-13.4179, 16.642) -> (-10, 16.0316)
  line L3 (-25.5, 0) -> (-25.5, 4.935)
  line L4 (-22.5, 0) -> (-25.5, 0)
  line L5 (-22.5, 4.3626) -> (-22.5, 0)
  curve K1 (-22.5, 4.3626) -> (-18.1183, 6.0086)
  curve K2 (-15, 0) -> (-18.1183, 6.0086)
  line L6 (15, 0) -> (-15, 0)
  curve K3 (15, 0) -> (18.1183, 6.0086)
  curve K4 (22.5, 4.3626) -> (18.1183, 6.0086)
  line L7 (22.5, 0) -> (22.5, 4.3626)
  line L8 (25.5, 0) -> (22.5, 0)
  line L9 (25.5, 4.935) -> (25.5, 0)
  line L10 (10, 16.0316) -> (13.4179, 16.642)
  line L11 (10, 11.9684) -> (-10, 11.9684)
  curve K5 (12.1729, 8.1647) -> (10, 11.9684)
  curve K6 (12.1729, 8.1647) -> (10.6866, 5.436)
  curve K7 (8.4244, 4) -> (10.6866, 5.436)
  line L12 (-8.4244, 4) -> (8.4244, 4)
  curve K8 (-8.4244, 4) -> (-10.6866, 5.436)
  curve K9 (-12.1729, 8.1647) -> (-10.6866, 5.436)
  curve K10 (-12.1729, 8.1647) -> (-10, 11.9684)
  line L13 (0.3581, 11.9684) -> (-3.8045, 4)
  line L14 (-0.4198, 4) -> (3.7427, 11.9684)
  arc A1 centre (-9.199, 40.2682) radius 24 clockwise from (-13.4179, 16.642) to (-21.8856, 19.8955)
  arc A2 centre (-24, 16.5) radius 4 clockwise from (-27.6429, 14.8479) to (-21.8856, 19.8955)
  arc A3 centre (-49.5, 4.935) radius 24 clockwise from (-27.6429, 14.8479) to (-25.5, 4.935)
  arc A4 centre (49.5, 4.935) radius 24 clockwise from (25.5, 4.935) to (27.6429, 14.8479)
  arc A5 centre (24, 16.5) radius 4 clockwise from (21.8856, 19.8955) to (27.6429, 14.8479)
  arc A6 centre (9.199, 40.2682) radius 24 clockwise from (21.8856, 19.8955) to (13.4179, 16.642)
  circle C1 centre (24, 16.5) radius 1.55
  circle C2 centre (-24, 16.5) radius 1.55
  point P41 (-0.4198, 4)
  point P38 (-3.8045, 4)
  point P40 (3.7427, 11.9684)
  point P39 (0.3581, 11.9684)
  coincident L12 P41
  parallel L13 L14
  coincident L12 P38
  coincident L11 P40
  coincident L11 P39
  dimension "d252" distance L13 L14 = 3
extrude "Extrude12" add sketch "center-lower-holes" profile of L12 L13 L14 against normal blind 2
fillet "Fillet31" radius 2
mirror "Mirror12" mirrorStitchTolerance 0.1
fillet "Fillet22" radius 6
extrude "Extrude11" new body sketch "center-lower" profile of L23 L25 C7 L29 L49 L50 L51 L52 L53 along normal blind 2 bodies "center-lower"
mirror "Mirror13" mirrorStitchTolerance 0.1
combine "Combine3"
fillet "Fillet28" radius 8
fillet "Fillet29" radius 5
fillet "Fillet30" radius 2
sketch "cam-mount-base" plane through (0, 0, 0) normal (0, 0, 1) x axis (1, 0, 0)
  line L1 (135, 0) -> (0, 0)
  line L2 (-104.9665, -10.02) -> (-84.9265, -10.02)
  line L3 (-104.9665, 10.02) -> (-104.9665, -10.02)
  line L4 (-84.9265, 10.02) -> (-104.9665, 10.02)
  line L5 (-84.9265, -10.02) -> (-84.9265, 10.02)
  line L6 (-165, 0) -> (0, 0)
  point P1 (0, 0)
  point P2 (0, 0)
  point P8 (0, 0)
  coincident P1 P2
  horizontal L1
  horizontal L2
  vertical L3
  horizontal L4
  vertical L5
  coincident P1 P8
  parallel L1 L6
  dimension "d275" distance L1 L2 = 10.02 (= "d276 / 2")
  dimension "d276" distance L2 L4 = 20.04
  dimension "d277" distance L3 L5 = 20.04 (= "d276")
extrude "Extrude15" new body sketch "cam-mount-base" profile of L2 L3 L4 L5 along normal blind 13 bodies "cam-mount-shell"
work_plane "WorkPlane1" sketch "cam-mount-base" AlongDistance 22.6
sketch "cam-mount-lens" plane through (0, 0, 22.6) normal (0, 0, 1) x axis (1, 0, 0)
  line L1 (-104.9665, 10.02) -> (-84.9265, 10.02)
  line L2 (-104.9665, -10.02) -> (-104.9665, 10.02)
  line L3 (-84.9265, -10.02) -> (-104.9665, -10.02)
  line L4 (-84.9265, 10.02) -> (-84.9265, -10.02)
  line L5 (-165, 0) -> (0, 0)
  line L6 (-94.9465, 10.02) -> (-94.9465, -10.02)
  circle C1 centre (-94.9465, 0) radius 7
  point P6 (-94.9465, 0)
  point P9 (-94.9465, -10.02)
  point P10 (-94.9465, 10.02)
  coincident P6 L5
  midpoint L3 P9
  midpoint L1 P10
  coincident P6 L6
  dimension "d281" diameter C1 = 14
loft "Loft1" sketch "cam-mount-lens"
shell "Shell1" outerThickness 1.5
extrude "Extrude16" add of existing geometry blind 2
move "Move1"
move "Move2"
